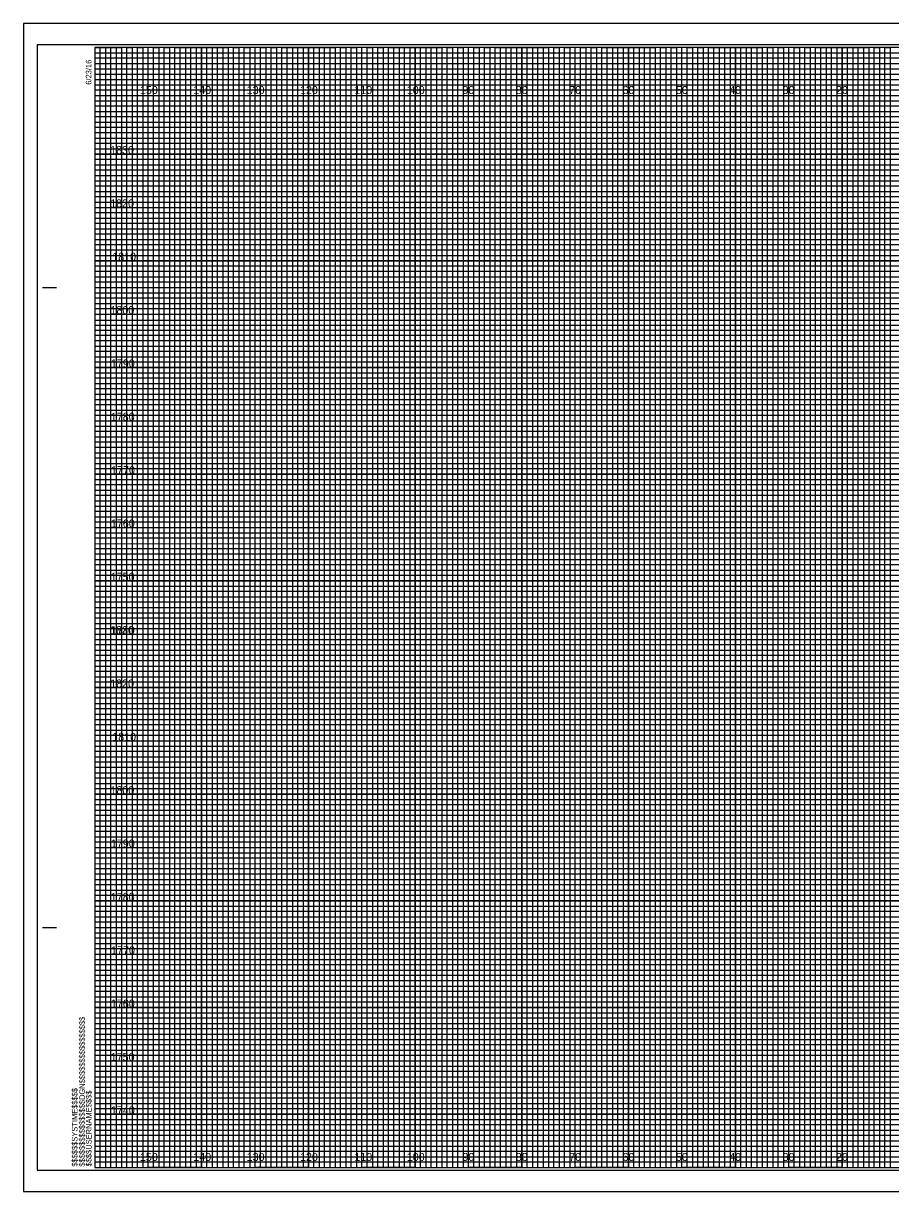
# Model space of a CAD drawing. Extents: x -13 to 323, y -5 to 654.
# Drawn here: x -13.4 to 149.1, y 215.5 to 434.5 of the extents above; entities that cross this region are included whole.
import ezdxf

# ---------------------------------------------------------------- set-up
doc = ezdxf.new("R2010")
doc.units = 0
for name, color, linetype in [('Prop XS DDE', 7, 'Continuous'), ('Prop XS Earthwork Shape', 7, 'Continuous'), ('Raster_Level_0', 7, 'Continuous'), ('Scratch_Level_3', 7, 'Continuous'), ('Sheet Cross Section CELL', 7, 'Continuous'), ('Sheet Cross Section Grid Minor 1 CELL', 7, 'Continuous'), ('Sheet Cross Section Grid Minor 2 CELL', 7, 'Continuous'), ('Sheet Cutting Line CELL', 7, 'Continuous'), ('Sheet DOT Grid CELL', 7, 'Continuous'), ('Sheet Plot Border Inside CELL', 7, 'Continuous'), ('Sheet Plot Border Outside CELL', 7, 'Continuous')]:
    doc.layers.add(name, color=color, linetype=linetype)

msp = doc.modelspace()

# ---------------------------------------------------------------- linework, layer by layer
at = {"layer": 'Prop XS DDE'}
for points in [[(0, 430), (5, 430), (5, 220), (15, 220), (15, 430), (25, 430), (25, 220), (35, 220), (35, 430), (45, 430), (45, 220), (55, 220), (55, 430), (65, 430), (65, 220), (75, 220), (75, 430), (85, 430), (85, 220), (95, 220), (95, 430), (105, 430), (105, 220), (115, 220), (115, 430), (125, 430), (125, 220), (135, 220), (135, 430), (145, 430), (145, 220), (155, 220)], [(0, 425), (275, 425)], [(0, 405), (320, 405), (320, 415), (0, 415)], [(0, 385), (320, 385), (320, 395), (0, 395)], [(0, 365), (320, 365), (320, 375), (0, 375)], [(0, 345), (320, 345), (320, 355), (0, 355)], [(0, 325), (320, 325), (320, 335), (0, 335)], [(0, 305), (320, 305), (320, 315), (0, 315)], [(0, 285), (320, 285), (320, 295), (0, 295)], [(0, 265), (320, 265), (320, 275), (0, 275)], [(0, 245), (320, 245), (320, 255), (0, 255)], [(0, 225), (320, 225), (320, 235), (0, 235)]]:
    msp.add_lwpolyline(points, dxfattribs=at)
at = {"layer": 'Prop XS Earthwork Shape'}
for p, q in [((10, 430), (0, 430)), ((10, 220), (10, 430)), ((30, 430), (20, 430)), ((20, 430), (20, 220)), ((30, 220), (30, 430)), ((50, 430), (40, 430)), ((40, 430), (40, 220)), ((50, 220), (50, 430)), ((70, 430), (60, 430)), ((60, 430), (60, 220)), ((70, 220), (70, 430)), ((90, 430), (80, 430)), ((80, 430), (80, 220)), ((90, 220), (90, 430)), ((110, 430), (100, 430)), ((100, 430), (100, 220)), ((110, 220), (110, 430)), ((130, 430), (120, 430)), ((120, 430), (120, 220)), ((130, 220), (130, 430)), ((150, 430), (140, 430)), ((140, 430), (140, 220)), ((20, 220), (10, 220)), ((40, 220), (30, 220)), ((60, 220), (50, 220)), ((80, 220), (70, 220)), ((100, 220), (90, 220)), ((120, 220), (110, 220)), ((140, 220), (130, 220))]:
    msp.add_line(p, q, dxfattribs=at)
for points in [[(0, 420), (320, 420), (320, 410), (0, 410)], [(0, 400), (320, 400), (320, 390), (0, 390)], [(0, 380), (320, 380), (320, 370), (0, 370)], [(0, 360), (320, 360), (320, 350), (0, 350)], [(0, 340), (320, 340), (320, 330), (0, 330)], [(0, 320), (320, 320), (320, 310), (0, 310)], [(0, 300), (320, 300), (320, 290), (0, 290)], [(0, 280), (320, 280), (320, 270), (0, 270)], [(0, 260), (320, 260), (320, 250), (0, 250)], [(0, 240), (320, 240), (320, 230), (0, 230)]]:
    msp.add_lwpolyline(points, dxfattribs=at)
at = {"layer": 'Sheet Cross Section CELL'}
for p, q in [((-9.8, 385), (-7.3, 385)), ((-9.7, 385), (-7.2, 385)), ((-9.8, 265), (-7.3, 265)), ((-9.7, 265), (-7.2, 265)), ((0, 220), (0, 220)), ((0, 220), (0, 220)), ((0, 220), (0, 220)), ((0, 220), (0, 220)), ((0, 220), (0, 220)), ((0, 220), (0, 220)), ((0, 220), (0, 220))]:
    msp.add_line(p, q, dxfattribs=at)
msp.add_lwpolyline([(320, 430), (0, 430), (0, 220), (320, 220)], close=True, dxfattribs=at)
at = {"layer": 'Sheet Cross Section Grid Minor 1 CELL'}
for p, q in [((0, 429), (260, 429)), ((260, 427.98), (0, 427.98)), ((0, 427.98), (0, 427)), ((0, 427), (260, 427)), ((260, 425.89), (0, 425.89)), ((0, 425.89), (0, 424)), ((0, 424), (320, 424))]:
    msp.add_line(p, q, dxfattribs=at)
for points in [[(0, 423), (270, 423), (320, 423), (320, 422), (0, 422)], [(0, 421), (320, 421), (320, 419), (0, 419)], [(0, 418), (320, 418), (320, 417), (0, 416.98)], [(0, 416), (320, 416), (320, 414), (0, 414)], [(0, 413), (320, 413), (320, 412), (0, 412)], [(0, 411), (320, 411), (320, 409), (0, 409)], [(0, 408), (320, 408), (320, 407), (0, 407)], [(0, 406), (320, 406), (320, 404), (0, 404)], [(0, 403), (320, 403), (320, 402), (0, 402)], [(0, 401), (320, 401), (320, 399), (0, 399)], [(0, 398), (320, 398), (320, 397), (0, 397)], [(0, 396), (320, 396), (320, 393.95), (320, 393), (320, 392), (0, 392)], [(0, 394), (320, 394), (320, 393), (0, 393)], [(0, 391), (320, 391), (320, 389), (0, 389.03)], [(0, 389.03), (320, 389), (320, 388), (0, 388)], [(0, 387), (320, 387), (320, 386), (0, 386)], [(0, 384), (320, 384), (320, 383), (0, 383)], [(0, 382), (320, 382), (320, 381), (0, 381)], [(-0.07, 378.89), (320, 378.89), (320, 377.88), (-0.07, 377.88)], [(0, 377), (320, 377), (320, 376), (0, 376)], [(0, 374), (320, 374), (320, 373), (0, 373)], [(0, 372), (320, 372), (320, 371), (0, 371)], [(0, 369), (320, 369), (320, 368), (0, 368)], [(0, 367), (320, 367), (320, 366), (0, 366)], [(0, 364), (320, 364), (320, 363), (0, 363)], [(0, 362), (320, 362), (320, 361), (0, 361)], [(0, 359), (320, 359), (319.99, 357.98), (0, 358)], [(0, 357), (320, 357), (320, 356), (0, 356)], [(0, 354), (320, 354), (320, 353), (0, 353)], [(0, 352), (320, 352), (320, 351), (0, 351)], [(0, 349), (320, 349), (320, 348), (0, 348)], [(0, 347), (320, 347), (320, 346), (0, 346)], [(0, 344), (320, 344), (320, 343), (0, 343)], [(0, 342), (320, 342), (320, 341), (0, 341)], [(0, 339), (320, 339), (320, 338), (0, 338)], [(0, 336.99), (320.07, 336.91), (320, 336), (0, 336)], [(0, 334), (320, 334), (320, 333), (0, 333)], [(0, 332), (320, 332), (320, 331), (0, 331)], [(0, 329), (320, 329), (320, 328), (0, 328)], [(0, 327), (320, 327), (320, 326), (0, 326)], [(0, 324), (320, 324), (320, 323), (0, 323)], [(0, 322), (320, 322), (320, 321), (0, 321)], [(0, 319), (320, 319), (320, 318), (0, 318)], [(0, 317), (320, 317), (320, 316), (0, 316)], [(0, 314), (320, 314), (320, 313), (0, 313)], [(0, 312), (320, 312), (320, 311), (0, 311)], [(0, 309), (320, 309), (320, 308), (0, 308)], [(0, 307), (320, 307), (320, 306), (0, 306)], [(0, 304), (320, 304), (320, 303), (0, 303)], [(0, 302), (320, 302), (320, 301), (0, 301)], [(0, 299), (320, 299), (319.99, 297.98), (0, 298)], [(0, 297), (320, 297), (320, 296), (0, 296)], [(0, 294), (320, 294), (320, 293), (0, 293)], [(0, 292), (320, 292), (320, 291), (0, 291)], [(0, 289), (320, 289), (320, 288), (0, 288)], [(0, 287), (320, 287), (320, 286), (0, 286)], [(0, 284), (320, 284), (320, 283), (0, 283)], [(0, 282), (320, 282), (320, 281), (0, 281)], [(0, 279), (320, 279), (320, 278), (0, 278)], [(0, 276.99), (320.07, 276.91), (320, 276), (0, 276)], [(0, 274), (320, 274), (320, 273), (0, 273)], [(0, 272), (320, 272), (320, 271), (0, 271)], [(0, 269), (320, 269), (320, 268), (0, 268)], [(0, 267), (320, 267), (320, 266), (0, 266)], [(0, 264), (320, 264), (320, 263), (0, 263)], [(0, 262), (320, 262), (320, 261), (0, 261)], [(0, 259), (320, 259), (320, 258), (0, 258)], [(0, 257), (320, 257), (320, 256), (0, 256)], [(0, 254), (320, 254), (320, 253), (0, 253)], [(0, 252), (320, 252), (320, 251), (0, 251)], [(0, 249), (320, 249), (320, 248), (0, 248)], [(0, 247), (320, 247), (320, 246), (0, 246)], [(0, 244), (320, 244), (320, 243), (0, 243)], [(0, 242), (320, 242), (320, 241), (0, 241)], [(0, 239), (320, 239), (320, 238), (0, 238)], [(0, 237), (320, 237), (320, 236), (0, 236)], [(0, 234), (320, 234), (320, 233), (0, 233)], [(0, 232), (320, 232), (320, 231), (0, 231)], [(0, 229), (320, 229), (320, 228), (0, 228)], [(0, 227), (320, 227), (320, 226), (0, 226)], [(0, 224), (320, 224), (320, 223), (0, 223)], [(0, 222), (320, 222), (320, 221), (0, 221)]]:
    msp.add_lwpolyline(points, dxfattribs=at)
at = {"layer": 'Sheet Cross Section Grid Minor 2 CELL'}
for points in [[(0, 220), (1, 220), (1, 430), (2, 430), (2, 220)], [(2, 220), (3, 220), (3, 430), (4, 430), (4, 220)], [(5, 220), (6, 220), (6, 430), (7, 430), (7, 220)], [(7, 220), (8, 220), (8, 430), (9, 430), (9, 220)], [(10, 220), (11, 220), (11, 430), (12, 430), (12, 220)], [(12, 220), (13, 220), (13, 430), (14, 430), (14, 220)], [(15, 220), (16, 220), (16, 430), (17, 430), (17, 220)], [(17, 220), (18, 220), (18, 430), (19, 430), (19, 220)], [(20, 220), (21, 220), (21, 430), (22, 430), (22, 220)], [(22, 220), (23, 220), (23, 430), (24, 430), (24, 220)], [(25, 220), (26, 220), (26, 430), (27, 430), (27, 220)], [(27, 220), (28, 220), (28, 430), (29, 430), (29, 220)], [(30, 220), (31, 220), (31, 430), (32, 430), (32, 220)], [(32, 220), (33, 220), (33, 430), (34, 430), (34, 220)], [(35, 220), (36, 220), (36, 430), (37, 430), (37, 220)], [(37, 220), (38, 220), (38, 430), (39, 430), (39, 220)], [(40, 220), (41, 220), (41, 430), (42, 430), (42, 220)], [(42, 220), (43, 220), (43, 430), (44, 430), (44, 220)], [(45, 220), (46, 220), (46, 430), (47, 430), (47, 220)], [(47, 220), (48, 220), (48, 430), (49, 430), (49, 220)], [(50, 220), (51, 220), (51, 430), (52, 430), (52, 220)], [(52, 220), (53, 220), (53, 430), (54, 430), (54, 220)], [(55, 220), (56, 220), (56, 430), (57, 430), (57, 220)], [(57, 220), (58, 220), (58, 430), (59, 430), (59, 220)], [(60, 220), (61, 220), (61, 430), (62, 430), (62, 220)], [(62, 220), (63, 220), (63, 430), (64, 430), (64, 220)], [(65, 220), (66, 220), (66, 430), (67, 430), (67, 220)], [(67, 220), (68, 220), (68, 430), (69, 430), (69, 220)], [(70, 220), (71, 220), (71, 430), (72, 430), (72, 220)], [(72, 220), (73, 220), (73, 430), (74, 430), (74, 220)], [(75, 220), (76, 220), (76, 430), (77, 430), (77, 220)], [(77, 220), (78, 220), (78, 430), (79, 430), (79, 220)], [(80, 220), (81, 220), (81, 430), (82, 430), (82, 220)], [(82, 220), (83, 220), (83, 430), (84, 430), (84, 220)], [(85, 220), (86, 220), (86, 430), (87, 430), (87, 220)], [(87, 220), (88, 220), (88, 430), (89, 430), (89, 220)], [(90, 220), (91, 220), (91, 430), (92, 430), (92, 220)], [(92, 220), (93, 220), (93, 430), (94, 430), (94, 220)], [(95, 220), (96, 220), (96, 430), (97, 430), (97, 220)], [(97, 220), (98, 220), (98, 430), (99, 430), (99, 220)], [(100, 220), (101, 220), (101, 430), (102, 430), (102, 220)], [(102, 220), (103, 220), (103, 430), (104, 430), (104, 220)], [(105, 220), (106, 220), (106, 430), (107, 430), (107, 220)], [(107, 220), (108, 220), (108, 430), (109, 430), (109, 220)], [(110, 220), (111, 220), (111, 430), (112, 430), (112, 220)], [(112, 220), (113, 220), (113, 430), (114, 430), (114, 220)], [(115, 220), (116, 220), (116, 430), (117, 430), (117, 220)], [(117, 220), (118, 220), (118, 430), (119, 430), (119, 220)], [(120, 220), (121, 220), (121, 430), (122, 430), (122, 220)], [(122, 220), (123, 220), (123, 430), (124, 430), (124, 220)], [(125, 220), (126, 220), (126, 430), (127, 430), (127, 220)], [(127, 220), (128, 220), (128, 430), (129, 430), (129, 220)], [(130, 220), (131, 220), (131, 430), (132, 430), (132, 220)], [(132, 220), (133, 220), (133, 430), (134, 430), (134, 220)], [(135, 220), (136, 220), (136, 430), (137, 430), (137, 220)], [(137, 220), (138, 220), (138, 430), (139, 430), (139, 220)], [(140, 220), (141, 220), (141, 430), (142, 430), (142, 220)], [(142, 220), (143, 220), (143, 430), (144, 430), (144, 220)], [(145, 220), (146, 220), (146, 430), (147, 430), (147, 220)], [(147, 220), (148, 220), (148, 430), (149, 430), (149, 220)]]:
    msp.add_lwpolyline(points, dxfattribs=at)
at = {"layer": 'Sheet Cutting Line CELL'}
for p, q in [((323.3, 434.5), (-13.4, 434.5)), ((-13.4, 434.5), (-13.4, 215.5)), ((-13.4, 215.5), (323.3, 215.5))]:
    msp.add_line(p, q, dxfattribs=at)
at = {"layer": 'Sheet DOT Grid CELL'}
for p, q in [((10, 220), (10, 430)), ((20, 220), (20, 430)), ((30, 220), (30, 430)), ((40, 220), (40, 430)), ((50, 220), (50, 430)), ((60, 220), (60, 430)), ((70, 220), (70, 430)), ((80, 220), (80, 430)), ((90, 220), (90, 430)), ((100, 220), (100, 430)), ((110, 220), (110, 430)), ((120, 220), (120, 430)), ((130, 220), (130, 430)), ((140, 220), (140, 430)), ((0, 420), (320, 420)), ((0, 410), (320, 410)), ((0, 400), (320, 400)), ((0, 390), (320, 390)), ((0, 380), (320, 380)), ((0, 370), (320, 370)), ((0, 360), (320, 360)), ((0, 350), (320, 350)), ((0, 340), (320, 340)), ((0, 330), (320, 330)), ((0, 320), (320, 320)), ((0, 310), (320, 310)), ((0, 300), (320, 300)), ((0, 290), (320, 290)), ((0, 280), (320, 280)), ((0, 270), (320, 270)), ((0, 260), (320, 260)), ((0, 250), (320, 250)), ((0, 240), (320, 240)), ((0, 230), (320, 230))]:
    msp.add_line(p, q, dxfattribs=at)
at = {"layer": 'Sheet Plot Border Inside CELL'}
msp.add_lwpolyline([(-10.8, 219.5), (322.4, 219.5), (322.4, 430.5), (-10.8, 430.5)], close=True, dxfattribs=at)
at = {"layer": 'Sheet Plot Border Outside CELL'}
msp.add_lwpolyline([(-13.4, 215.5), (323.3, 215.5), (323.3, 434.5), (-13.4, 434.5)], close=True, dxfattribs=at)

# ---------------------------------------------------------------- texts
at = {"layer": 'Raster_Level_0'}
for s, p in [('150', (8.44, 421.25)), ('140', (18.44, 421.25)), ('130', (28.44, 421.25)), ('120', (38.44, 421.25)), ('110', (48.62, 421.25)), ('100', (58.44, 421.25)), ('90', (68.86, 421.25)), ('80', (78.86, 421.25)), ('70', (88.86, 421.25)), ('60', (98.86, 421.25)), ('50', (108.86, 421.25)), ('40', (118.86, 421.25)), ('30', (128.86, 421.25)), ('20', (138.86, 421.25)), ('150', (8.44, 221.25)), ('140', (18.44, 221.25)), ('130', (28.44, 221.25)), ('120', (38.44, 221.25)), ('110', (48.62, 221.25)), ('100', (58.44, 221.25)), ('90', (68.86, 221.25)), ('80', (78.86, 221.25)), ('70', (88.86, 221.25)), ('60', (98.86, 221.25)), ('50', (108.86, 221.25)), ('40', (118.86, 221.25)), ('30', (128.86, 221.25)), ('20', (138.86, 221.25))]:
    msp.add_text(s, height=1.5, dxfattribs=at).set_placement(p)
at = {"layer": 'Scratch_Level_3'}
for s, p in [('1830', (2.86, 410)), ('1820', (2.87, 400)), ('1810', (3.25, 390)), ('1800', (2.92, 380)), ('1790', (3, 370)), ('1780', (2.98, 360)), ('1770', (3.04, 350)), ('1760', (3, 340)), ('1750', (2.96, 330)), ('1830', (2.86, 320)), ('1740', (3, 320)), ('1820', (2.87, 310)), ('1810', (3.25, 300)), ('1800', (2.92, 290)), ('1790', (3, 280)), ('1780', (2.98, 270)), ('1770', (3.04, 260)), ('1760', (3, 250)), ('1750', (2.96, 240)), ('1740', (3, 230))]:
    msp.add_text(s, height=1.5, dxfattribs=at).set_placement(p)
at = {"layer": 'Sheet Cross Section CELL'}
for s, p in [('6/23/16', (-0.65, 423)), ('$$$$$$$$$$$$$$$$DGN$$$$$$$$$$$$$$$$', (-1.88, 220.18)), ('$$$$$$SYSTIME$$$$$', (-3.26, 220.18)), ('$$$$USERNAME$$$$', (-0.62, 220.23))]:
    msp.add_text(s, height=1.05, rotation=90, dxfattribs=at).set_placement(p)

doc.saveas('drawing.dxf')
